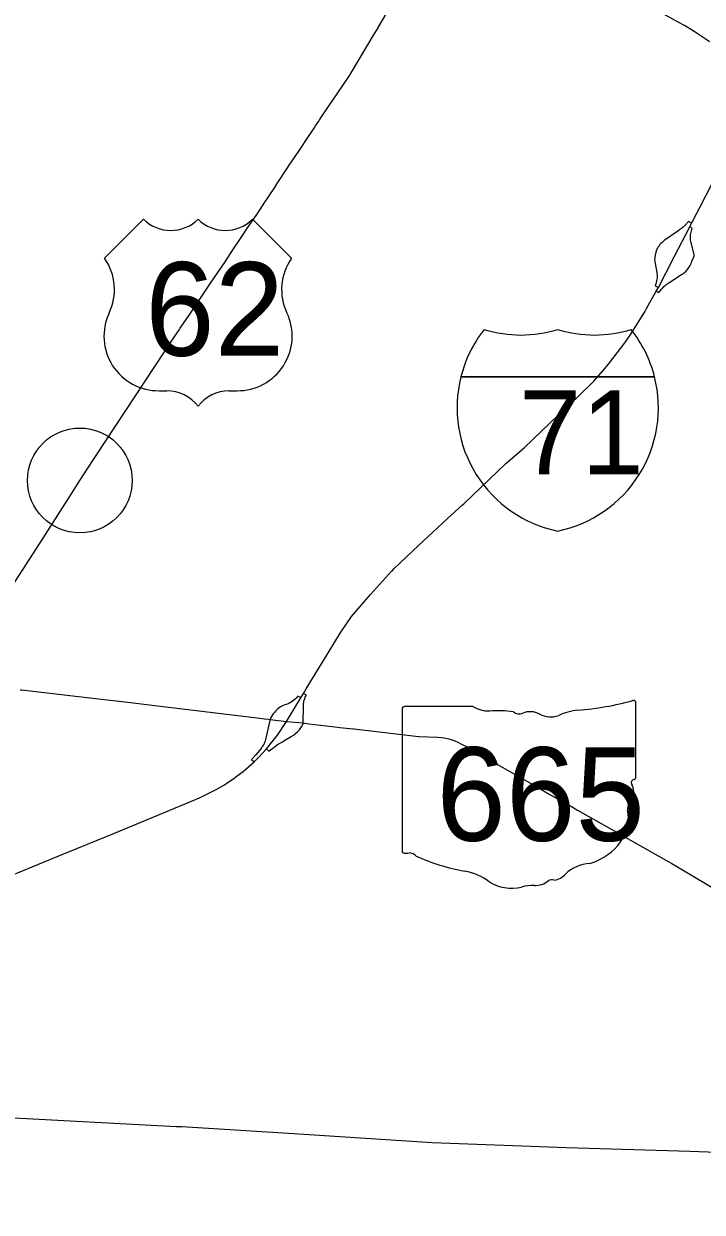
# Model space of a CAD drawing. Extents: x 0 to 34, y 0 to 22.
# Drawn here: x 4.137 to 5.072, y 14.434 to 16.072 of the extents above; entities that cross this region are included whole.
import ezdxf

# ---------------------------------------------------------------- set-up
doc = ezdxf.new("R2010")
doc.units = 0
for name, color, linetype in [('GM_X_County', 7, 'Continuous'), ('GM_X_Interchange_Ramps', 7, 'Continuous'), ('GM_X_Interstate_Route', 7, 'Continuous'), ('GM_X_Interstate_Shield', 7, 'Continuous'), ('GM_X_State_Route', 7, 'Continuous'), ('GM_X_State_Shield', 7, 'Continuous'), ('GM_X_US_Route', 7, 'Continuous'), ('GM_X_US_Shield', 7, 'Continuous'), ('SH_Text', 7, 'Continuous')]:
    doc.layers.add(name, color=color, linetype=linetype)

msp = doc.modelspace()

# ---------------------------------------------------------------- linework, layer by layer
at = {"layer": 'GM_X_County'}
msp.add_lwpolyline([(6.4853, 14.4341), (6.2434, 14.4473), (6.2427, 14.4474), (5.9966, 14.4624), (5.7606, 14.4783), (5.6711, 14.4822), (5.513, 14.4923), (5.4918, 14.4937), (5.3167, 14.5061), (5.2797, 14.5085), (5.0939, 14.5163), (5.08, 14.5169), (5.0551, 14.5178), (4.8851, 14.5227), (4.6999, 14.5295), (4.5093, 14.542), (4.3546, 14.5516), (4.3469, 14.5519), (4.1065, 14.5646)], dxfattribs=at)
at = {"layer": 'GM_X_Interchange_Ramps'}
for points in [[(5.0576, 15.7971), (5.0533, 15.7994), (5.0491, 15.7948), (5.0478, 15.7935), (5.0463, 15.792), (5.0452, 15.791), (5.0436, 15.7898), (5.0425, 15.7888), (5.0409, 15.7877), (5.0387, 15.7862), (5.0196, 15.7729), (5.0182, 15.7718), (5.0168, 15.7706), (5.0154, 15.7691), (5.0139, 15.7674), (5.0127, 15.7659), (5.0117, 15.7644), (5.0107, 15.7627), (5.0098, 15.761), (5.0087, 15.7587), (5.0069, 15.7511), (5.0067, 15.749)], [(5.0613, 15.7521), (5.0612, 15.754), (5.0565, 15.7718), (5.0563, 15.7736), (5.0562, 15.7754), (5.0561, 15.7771), (5.0562, 15.779), (5.0563, 15.7808), (5.0566, 15.7827), (5.0569, 15.7844), (5.0573, 15.7863), (5.0585, 15.7903), (5.055, 15.7921)], [(5.0067, 15.749), (5.0066, 15.7464), (5.0095, 15.7291), (5.0098, 15.7274), (5.0099, 15.7255), (5.01, 15.7237), (5.0099, 15.7218), (5.0097, 15.7199), (5.0094, 15.7181), (5.0091, 15.7166), (5.0086, 15.7147), (5.0074, 15.7108), (5.0118, 15.7084)], [(5.0089, 15.7031), (5.0122, 15.7013), (5.0165, 15.7064), (5.0175, 15.7075), (5.0184, 15.7085), (5.0195, 15.7096), (5.0206, 15.7106), (5.0223, 15.712), (5.0237, 15.713), (5.0253, 15.7142), (5.0274, 15.7155), (5.0436, 15.7262), (5.0453, 15.7273), (5.0468, 15.7283), (5.0482, 15.7295), (5.0495, 15.7306), (5.0509, 15.7321), (5.0519, 15.7332), (5.053, 15.7346), (5.054, 15.736), (5.0549, 15.7375), (5.0557, 15.7389), (5.0564, 15.7403), (5.057, 15.7416), (5.0576, 15.7432), (5.058, 15.7443), (5.0584, 15.7455), (5.0608, 15.7504), (5.0613, 15.7521)], [(4.522, 15.1083), (4.5221, 15.1104), (4.5223, 15.13), (4.5224, 15.132), (4.5225, 15.1337), (4.5227, 15.135), (4.5229, 15.1367), (4.5232, 15.1381), (4.5236, 15.1395), (4.524, 15.1408), (4.5245, 15.1422), (4.525, 15.1436), (4.5265, 15.1467), (4.5226, 15.1491)], [(4.5188, 15.1427), (4.5148, 15.1451), (4.5123, 15.1425), (4.5109, 15.1411), (4.5093, 15.1397), (4.5075, 15.1384), (4.5055, 15.137), (4.5038, 15.1361), (4.5021, 15.1352), (4.5002, 15.1344), (4.4984, 15.1336), (4.4966, 15.1331), (4.4946, 15.1323), (4.4928, 15.1314), (4.4908, 15.1303), (4.4888, 15.129), (4.487, 15.1276), (4.4852, 15.1261), (4.4838, 15.1246), (4.4824, 15.1229), (4.4808, 15.1208), (4.4797, 15.1195), (4.4783, 15.1174), (4.477, 15.1151), (4.4764, 15.1131)], [(4.4764, 15.1131), (4.4763, 15.1116), (4.4701, 15.0854), (4.4696, 15.0837), (4.4691, 15.0823), (4.4684, 15.0806), (4.4676, 15.0788), (4.4668, 15.0775), (4.4662, 15.0763), (4.4655, 15.0754), (4.4648, 15.0743), (4.4641, 15.0733), (4.4568, 15.0642), (4.4508, 15.058), (4.4543, 15.0545)], [(4.4717, 15.0727), (4.4749, 15.0695), (4.4774, 15.0715), (4.4796, 15.0732), (4.4822, 15.0751), (4.4845, 15.0767), (4.4869, 15.0784), (4.4895, 15.0801), (4.4926, 15.082), (4.4953, 15.0837), (4.4977, 15.0851), (4.5, 15.0864), (4.5053, 15.0896), (4.5086, 15.0915), (4.5108, 15.0931), (4.5125, 15.0945), (4.5142, 15.0962), (4.5156, 15.0976), (4.5168, 15.099), (4.5178, 15.1004), (4.5199, 15.1031), (4.5219, 15.1069), (4.522, 15.1083)]]:
    msp.add_lwpolyline(points, dxfattribs=at)
at = {"layer": 'GM_X_Interstate_Route'}
for points in [[(5.0476, 16.0692), (5.0393, 16.0741), (5.0103, 16.0902), (4.9969, 16.0959), (4.9743, 16.1056), (4.9528, 16.1135), (4.9223, 16.1222), (4.8603, 16.1389), (4.8445, 16.1429), (4.8016, 16.154), (4.7767, 16.1604), (4.7534, 16.1664), (4.7429, 16.1692), (4.7137, 16.1764), (4.6951, 16.1813)], [(5.0822, 16.0471), (5.0791, 16.0493), (5.0611, 16.0611), (5.0476, 16.0692)], [(5.0646, 15.8106), (5.0692, 15.8195), (5.0852, 15.85), (5.1016, 15.8784), (5.1116, 15.8944)], [(5.0588, 15.7993), (5.0646, 15.8106)], [(5.0337, 15.7504), (5.0337, 15.7504), (5.055, 15.7921), (5.0576, 15.7971), (5.0588, 15.7993)], [(4.9956, 15.6795), (5.0089, 15.7031), (5.0118, 15.7084), (5.0337, 15.7504)], [(4.9352, 15.5937), (4.9429, 15.6027), (4.9656, 15.6323), (4.9737, 15.6439), (4.993, 15.6748), (4.9956, 15.6795)], [(4.8734, 15.5318), (4.8837, 15.5415), (4.9008, 15.5578), (4.9227, 15.5792), (4.9352, 15.5937)], [(4.7419, 15.4088), (4.7438, 15.4104), (4.8014, 15.466), (4.8267, 15.4875), (4.8627, 15.5218), (4.8734, 15.5318)], [(4.644, 15.3174), (4.6452, 15.3186), (4.6472, 15.3208), (4.6813, 15.3528), (4.7205, 15.3898), (4.7419, 15.4087), (4.7419, 15.4088)], [(4.5561, 15.2042), (4.5729, 15.2321), (4.5887, 15.2549), (4.6147, 15.2855), (4.644, 15.3174)], [(4.5264, 15.1554), (4.5525, 15.1982), (4.5561, 15.2042)], [(4.4991, 15.1105), (4.5188, 15.1427), (4.5226, 15.1491), (4.5264, 15.1554)], [(4.431, 15.0352), (4.4393, 15.0414), (4.4543, 15.0545), (4.4605, 15.0607), (4.4717, 15.0727), (4.4866, 15.0915), (4.4991, 15.1105)], [(4.4186, 15.0266), (4.4251, 15.0308), (4.431, 15.0352)], [(4.1248, 14.9006), (4.1271, 14.9015), (4.1854, 14.9253), (4.2621, 14.9566), (4.3218, 14.9814), (4.379, 15.0051), (4.4021, 15.0166), (4.4136, 15.0232), (4.4186, 15.0266)]]:
    msp.add_lwpolyline(points, dxfattribs=at)
at = {"layer": 'GM_X_Interstate_Shield'}
for p, q in [((4.7394, 15.5854), (5.0065, 15.5854)), ((5.0065, 15.5854), (4.7394, 15.5854)), ((5.0065, 15.5854), (4.7394, 15.5854))]:
    msp.add_line(p, q, dxfattribs=at)
for centre, start, end in [((4.9077, 15.5428), 141.669, 165.8066), ((4.8223, 15.8164), 253.0091, 286.9909), ((4.9237, 15.8164), 253.0091, 286.9909), ((4.8383, 15.5428), 14.1934, 38.331), ((4.9077, 15.5428), 165.8066, 258.463), ((4.8383, 15.5428), 281.537, 14.1934)]:
    msp.add_arc(centre, 0.1735, start, end, dxfattribs=at)
at = {"layer": 'GM_X_State_Route'}
for points in [[(4.1317, 15.1541), (4.1339, 15.1538), (4.2478, 15.1407), (4.2727, 15.1378), (4.3329, 15.1306), (4.3973, 15.1229), (4.4585, 15.1153), (4.4659, 15.1145)], [(4.4659, 15.1145), (4.4683, 15.1142), (4.4744, 15.1133)], [(4.4744, 15.1133), (4.4764, 15.1131), (4.4991, 15.1105), (4.522, 15.1083), (4.5297, 15.1071)], [(4.5297, 15.1071), (4.5457, 15.1052), (4.5465, 15.1052)], [(4.5465, 15.1052), (4.5656, 15.1029)], [(4.5656, 15.1029), (4.5726, 15.102), (4.5727, 15.102)], [(4.5727, 15.102), (4.5908, 15.1002), (4.5917, 15.1), (4.5919, 15.1)], [(4.5919, 15.1), (4.6196, 15.0968), (4.6811, 15.0897), (4.6818, 15.0896), (4.7073, 15.0889), (4.7129, 15.0883), (4.7164, 15.0879)], [(4.7164, 15.0879), (4.7188, 15.0875), (4.7228, 15.0865), (4.726, 15.0855), (4.7288, 15.0846), (4.732, 15.0834), (4.7342, 15.0825), (4.7415, 15.0786)], [(4.7415, 15.0786), (4.748, 15.0752)], [(4.748, 15.0752), (4.7498, 15.0743), (4.7899, 15.0511), (4.8484, 15.0181), (4.8611, 15.0103), (4.8918, 14.9931), (4.9001, 14.9882), (4.9474, 14.9613), (4.9693, 14.949)], [(4.9693, 14.949), (4.9733, 14.9467)], [(4.9733, 14.9467), (5.0253, 14.9173), (5.0305, 14.9147), (5.0915, 14.8785), (5.0945, 14.8768), (5.0974, 14.876), (5.1007, 14.8745), (5.1041, 14.8734), (5.1064, 14.8728), (5.1064, 14.8727)]]:
    msp.add_lwpolyline(points, dxfattribs=at)
at = {"layer": 'GM_X_State_Shield'}
for p, q in [((4.9807, 15.0336), (4.9807, 15.1359)), ((4.6586, 15.1277), (4.6586, 14.9321)), ((4.7561, 15.131), (4.6618, 15.131)), ((4.9807, 15.0336), (4.9807, 15.0336))]:
    msp.add_line(p, q, dxfattribs=at)
for centre, major_axis, start_param, end_param in [((4.866, 15.3977), (0.3416, 0), 4.814394, 5.042369), ((4.9771, 15.1363), (0.00359, 0), 6.141152, 7.989035), ((4.6623, 15.1281), (0.00373, 0), 1.712693, 3.28349), ((4.7786, 15.1538), (0.0362, 0), 4.042523, 4.731795), ((4.7906, 15.0212), (0.1299, 0), 1.404758, 1.657858), ((4.8201, 15.1291), (0.0104, 0), 3.836095, 5.185415), ((4.8354, 15.1065), (0.0217, 0), 0.950623, 2.079405), ((4.8634, 15.1375), (0.0261, 0), 4.081561, 5.145723), ((4.9095, 15.0713), (0.0687, 0), 1.699011, 2.107814), ((4.9799, 15.0261), (0.00555, 0), 1.883978, 3.671073), ((4.9446, 15.0131), (0.0333, 0), 5.934695, 6.695948), ((4.9769, 15.0332), (0.00384, 0), 5.05454, 6.418171), ((4.9936, 14.9908), (0.0242, 0), 2.387724, 3.262537), ((4.8851, 14.9778), (0.0854, 0), 5.101752, 6.440018), ((4.6623, 14.9317), (0.00376, 0), 3.00124, 4.508301), ((4.6629, 14.9517), (0.0287, 0), 4.665946, 4.897461), ((4.6688, 14.9208), (0.0104, 0), 0.519207, 1.627899), ((4.7996, 15.0965), (0.2467, 0), 4.195997, 4.488961), ((4.726, 14.8442), (0.0772, 0), 0.823519, 1.323587), ((4.9211, 14.8772), (0.0468, 0), 1.647645, 2.488434), ((4.8095, 14.9198), (0.049, 0), 4.026481, 4.996735), ((4.8414, 14.9052), (0.0261, 0), 4.691044, 5.507374), ((4.865, 14.8863), (0.00735, 0), 1.147584, 2.315152), ((4.8618, 14.9131), (0.0276, 0), 4.937069, 5.64225), ((4.8378, 14.8522), (0.0402, 0), 1.495662, 1.94098)]:
    msp.add_ellipse(centre, major_axis=major_axis, ratio=0.8, start_param=start_param, end_param=end_param, dxfattribs=at)
at = {"layer": 'GM_X_US_Route'}
for points in [[(4.5446, 15.9392), (4.5618, 15.9649), (4.5621, 15.9653), (4.5865, 16.0009), (4.5869, 16.0017), (4.6114, 16.0429), (4.6187, 16.0552), (4.6253, 16.0663), (4.6256, 16.0668), (4.6329, 16.0791), (4.636, 16.0844), (4.64, 16.0911), (4.6466, 16.1024), (4.6473, 16.1034), (4.6552, 16.1153), (4.6648, 16.1295)], [(4.5392, 15.9311), (4.5436, 15.9377), (4.5446, 15.9392)], [(4.4997, 15.8721), (4.5028, 15.8768), (4.52, 15.9024), (4.5248, 15.9096), (4.5382, 15.9295), (4.5392, 15.9311)], [(4.4837, 15.8475), (4.4839, 15.8478), (4.4875, 15.8539), (4.4879, 15.8545), (4.4996, 15.8719), (4.4997, 15.8721)], [(4.4564, 15.8064), (4.4591, 15.8105), (4.4627, 15.8159), (4.4693, 15.8258), (4.4735, 15.8321), (4.477, 15.8373), (4.4837, 15.8475)], [(4.4052, 15.7303), (4.4143, 15.7438), (4.4261, 15.7617), (4.4337, 15.7731), (4.4412, 15.784), (4.4435, 15.7877), (4.4559, 15.8056), (4.4564, 15.8064)], [(4.3706, 15.6786), (4.3749, 15.6852), (4.3944, 15.7142), (4.4052, 15.7303)], [(4.3527, 15.6521), (4.3651, 15.6703), (4.3706, 15.6786)], [(4.2222, 15.4551), (4.3177, 15.5996), (4.3452, 15.6412), (4.3516, 15.6503), (4.3527, 15.6521)], [(4.2142, 15.4425), (4.2142, 15.4425), (4.2209, 15.4531), (4.2222, 15.4551), (4.2222, 15.4551)], [(4.1137, 15.2857), (4.1159, 15.2891), (4.1638, 15.363), (4.2009, 15.4215), (4.2142, 15.4425)]]:
    msp.add_lwpolyline(points, dxfattribs=at)
at = {"layer": 'GM_X_US_Shield'}
for p, q in [((4.302, 15.8023), (4.2483, 15.7486)), ((4.506, 15.7486), (4.4523, 15.8023)), ((4.3235, 15.5661), (4.3342, 15.5661)), ((4.4201, 15.5661), (4.4308, 15.5661))]:
    msp.add_line(p, q, dxfattribs=at)
for centre, radius, start, end in [((4.3396, 15.8407), 0.0537, 225.573, 314.427), ((4.4147, 15.8407), 0.0537, 225.573, 314.427), ((4.1867, 15.7055), 0.0752, 334.5471, 35.0009), ((4.5676, 15.7055), 0.0752, 144.9991, 205.4529), ((4.3226, 15.6413), 0.0752, 154.8319, 270.6383), ((4.4317, 15.6413), 0.0752, 269.3617, 25.1681), ((4.3342, 15.5124), 0.0537, 36.8699, 90), ((4.4201, 15.5124), 0.0537, 90, 143.1301)]:
    msp.add_arc(centre, radius, start, end, dxfattribs=at)
at = {"layer": 'SH_Text'}
msp.add_circle((4.2142, 15.4425), 0.0722, dxfattribs=at)

# ---------------------------------------------------------------- texts
at = {"layer": 'GM_X_Interstate_Shield'}
msp.add_text('71', height=0.11569, dxfattribs=at).set_placement((4.8195, 15.4509))
at = {"layer": 'GM_X_State_Shield'}
msp.add_text('665', height=0.12885, dxfattribs=at).set_placement((4.7058, 14.9459))
at = {"layer": 'GM_X_US_Shield'}
msp.add_text('62', height=0.12885, dxfattribs=at).set_placement((4.3042, 15.6144))

doc.saveas('drawing.dxf')
